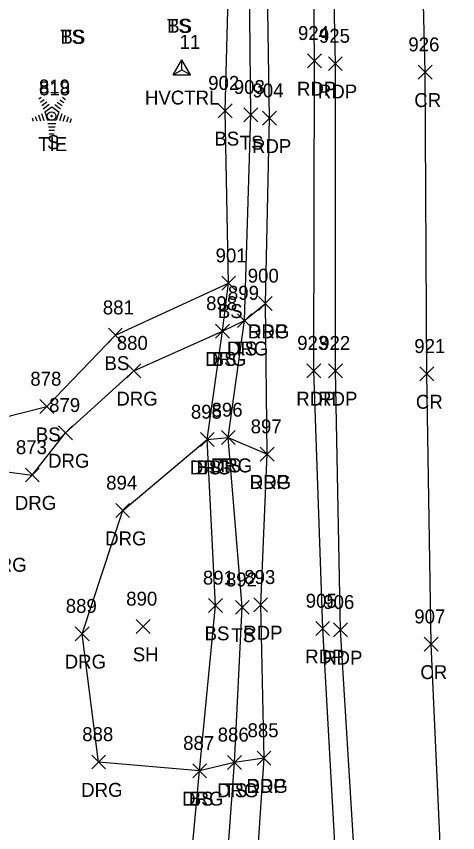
# Model space of a CAD drawing. Extents: x 1482574 to 1485769, y 580696 to 595649.
# Drawn here: x 1483637.4 to 1483700.8, y 584637.7 to 584755 of the extents above; entities that cross this region are included whole.
import ezdxf

# ---------------------------------------------------------------- set-up
doc = ezdxf.new("R2010")
doc.units = 0
for name, color, linetype in [('C_A', 7, 'Continuous'), ('C_I', 7, 'Continuous'), ('CBP', 7, 'Continuous'), ('CPSM', 7, 'Continuous'), ('L_A', 7, 'Continuous'), ('L_I', 7, 'Continuous'), ('L_TIC', 7, 'Continuous'), ('LELB', 7, 'Continuous'), ('LTC', 7, 'Continuous'), ('P_A', 7, 'Continuous'), ('P_I', 7, 'Continuous'), ('P_TIC', 7, 'Continuous'), ('PET', 7, 'Continuous'), ('PRC', 7, 'Continuous'), ('R_A', 7, 'Continuous'), ('R_I', 7, 'Continuous'), ('R_TIC', 7, 'Continuous'), ('RDG', 7, 'Continuous')]:
    doc.layers.add(name, color=color, linetype=linetype)

msp = doc.modelspace()

# ---------------------------------------------------------------- linework, layer by layer
at = {"layer": 'CBP'}
for radius in [0.625, 0.0833]:
    msp.add_circle((1483642.44, 584740.63), radius, dxfattribs=at)
at = {"layer": 'CPSM'}
for p, q in [((1483659.91, 584746.58), (1483661.16, 584748.75)), ((1483662.41, 584746.58), (1483661.16, 584748.75)), ((1483661.16, 584747.31), (1483661.16, 584748.75)), ((1483659.91, 584746.58), (1483661.16, 584747.31)), ((1483661.16, 584747.31), (1483661.16, 584747.31)), ((1483661.16, 584747.31), (1483662.41, 584746.58)), ((1483659.91, 584746.58), (1483662.41, 584746.58))]:
    msp.add_line(p, q, dxfattribs=at)
at = {"layer": 'L_TIC'}
for points in [[(1483666.38, 584740.41), (1483668.38, 584742.41)], [(1483668.38, 584740.41), (1483666.38, 584742.41)], [(1483670.07, 584739.83), (1483672.07, 584741.83)], [(1483672.07, 584739.83), (1483670.07, 584741.83)], [(1483666.88, 584715.64), (1483668.88, 584717.64)], [(1483668.88, 584715.64), (1483666.88, 584717.64)], [(1483666.88, 584715.64), (1483668.88, 584717.64)], [(1483668.88, 584715.64), (1483666.88, 584717.64)], [(1483669.14, 584710.27), (1483671.14, 584712.27)], [(1483671.14, 584710.27), (1483669.14, 584712.27)], [(1483666, 584708.77), (1483668, 584710.77)], [(1483668, 584708.77), (1483666, 584710.77)], [(1483650.6, 584708.17), (1483652.6, 584710.17)], [(1483652.6, 584708.17), (1483650.6, 584710.17)], [(1483640.74, 584697.93), (1483642.74, 584699.93)], [(1483642.74, 584697.93), (1483640.74, 584699.93)], [(1483666.83, 584693.48), (1483668.83, 584695.48)], [(1483668.83, 584693.48), (1483666.83, 584695.48)], [(1483663.81, 584693.19), (1483665.81, 584695.19)], [(1483665.81, 584693.19), (1483663.81, 584695.19)], [(1483664.98, 584669.36), (1483666.98, 584671.36)], [(1483666.98, 584669.36), (1483664.98, 584671.36)], [(1483668.84, 584669.1), (1483670.84, 584671.1)], [(1483670.84, 584669.1), (1483668.84, 584671.1)], [(1483654.61, 584666.34), (1483656.61, 584668.34)], [(1483656.61, 584666.34), (1483654.61, 584668.34)], [(1483667.72, 584646.82), (1483669.72, 584648.82)], [(1483669.72, 584646.82), (1483667.72, 584648.82)], [(1483662.71, 584645.62), (1483664.71, 584647.62)], [(1483664.71, 584645.62), (1483662.71, 584647.62)]]:
    msp.add_lwpolyline(points, dxfattribs=at)
at = {"layer": 'LELB'}
for points in [[(1483653.84, 584485.66), (1483655.16, 584497.25), (1483655.54, 584508.04), (1483660.89, 584522.88), (1483662.01, 584542.56), (1483663.9, 584573.36), (1483665.25, 584597.52), (1483666.54, 584618.22), (1483668.72, 584647.82), (1483669.84, 584670.1), (1483667.83, 584694.48), (1483670.14, 584711.27), (1483671.07, 584740.83), (1483670.56, 584792.73), (1483669.11, 584848.72), (1483666.77, 584902.21), (1483663.28, 584933.66), (1483662.05, 584942.07), (1483660.7, 584971.14), (1483662.19, 585003.59), (1483659.13, 585033.61), (1483657, 585045.7), (1483655.66, 585050.89), (1483655.43, 585083.72)], [(1483654.46, 584522.1), (1483653.65, 584530.37), (1483654.1, 584540.8), (1483656, 584573.95), (1483659.68, 584598.73), (1483657.74, 584615.24), (1483661.34, 584621.29), (1483663.71, 584646.62), (1483665.98, 584670.36), (1483664.81, 584694.19), (1483667, 584709.77), (1483667.88, 584716.64), (1483667.38, 584741.41), (1483668.7, 584792.15), (1483665.36, 584854.01), (1483663.91, 584902.17), (1483659.38, 584934.36), (1483656.14, 584945.72), (1483655.04, 584963.71), (1483656.17, 584970.54), (1483658.83, 585003.13), (1483656.92, 585033.59), (1483650.5, 585052.36), (1483650.21, 585078.55)], [(1483610.04, 584629.32), (1483609.43, 584646.28), (1483605.06, 584662.73), (1483601.74, 584679.59), (1483603.48, 584697.36), (1483628.88, 584695.71), (1483641.74, 584698.93), (1483651.6, 584709.17), (1483667.88, 584716.64)]]:
    msp.add_lwpolyline(points, dxfattribs=at)
at = {"layer": 'LTC'}
for p, q in [((1483640.61, 584743.11), (1483640.96, 584743.36)), ((1483640.82, 584742.64), (1483641.35, 584743.03)), ((1483641.03, 584742.18), (1483641.73, 584742.69)), ((1483641.24, 584741.71), (1483642.11, 584742.35)), ((1483642.89, 584742.3), (1483643.7, 584741.71)), ((1483643.26, 584742.65), (1483643.94, 584742.16)), ((1483643.63, 584743), (1483644.18, 584742.6)), ((1483644.01, 584743.35), (1483644.42, 584743.04)), ((1483641.46, 584741.25), (1483642.47, 584741.99)), ((1483641.46, 584741.25), (1483641.85, 584740.06)), ((1483642.47, 584741.99), (1483643.47, 584741.26)), ((1483643.47, 584741.26), (1483643.08, 584740.06)), ((1483639.64, 584740.39), (1483639.79, 584739.92)), ((1483640.1, 584740.6), (1483640.31, 584739.95)), ((1483640.55, 584740.82), (1483640.82, 584739.98)), ((1483641.01, 584741.04), (1483641.34, 584740.02)), ((1483643.08, 584740.06), (1483641.85, 584740.06)), ((1483643.91, 584740.99), (1483643.57, 584739.95)), ((1483644.35, 584740.74), (1483644.06, 584739.86)), ((1483644.8, 584740.49), (1483644.56, 584739.76)), ((1483645.24, 584740.24), (1483645.05, 584739.67)), ((1483643.04, 584739.56), (1483641.9, 584739.56)), ((1483642.96, 584739.06), (1483641.97, 584739.06)), ((1483642.87, 584738.56), (1483642.04, 584738.56)), ((1483642.79, 584738.06), (1483642.11, 584738.06))]:
    msp.add_line(p, q, dxfattribs=at)
at = {"layer": 'P_TIC'}
for points in [[(1483679.2, 584747.58), (1483681.2, 584749.58)], [(1483681.2, 584747.58), (1483679.2, 584749.58)], [(1483682.21, 584747.18), (1483684.21, 584749.18)], [(1483684.21, 584747.18), (1483682.21, 584749.18)], [(1483695.11, 584745.95), (1483697.11, 584747.95)], [(1483697.11, 584745.95), (1483695.11, 584747.95)], [(1483672.74, 584739.34), (1483674.74, 584741.34)], [(1483674.74, 584739.34), (1483672.74, 584741.34)], [(1483672.15, 584712.73), (1483674.15, 584714.73)], [(1483674.15, 584712.73), (1483672.15, 584714.73)], [(1483679.1, 584703.07), (1483681.1, 584705.07)], [(1483681.1, 584703.07), (1483679.1, 584705.07)], [(1483682.24, 584703.06), (1483684.24, 584705.06)], [(1483684.24, 584703.06), (1483682.24, 584705.06)], [(1483695.35, 584702.62), (1483697.35, 584704.62)], [(1483697.35, 584702.62), (1483695.35, 584704.62)], [(1483672.4, 584691.09), (1483674.4, 584693.09)], [(1483674.4, 584691.09), (1483672.4, 584693.09)], [(1483671.48, 584669.45), (1483673.48, 584671.45)], [(1483673.48, 584669.45), (1483671.48, 584671.45)], [(1483680.39, 584666.04), (1483682.39, 584668.04)], [(1483682.39, 584666.04), (1483680.39, 584668.04)], [(1483682.96, 584665.86), (1483684.96, 584667.86)], [(1483684.96, 584665.86), (1483682.96, 584667.86)], [(1483695.99, 584663.79), (1483697.99, 584665.79)], [(1483697.99, 584663.79), (1483695.99, 584665.79)], [(1483671.96, 584647.44), (1483673.96, 584649.44)], [(1483673.96, 584647.44), (1483671.96, 584649.44)]]:
    msp.add_lwpolyline(points, dxfattribs=at)
at = {"layer": 'PET'}
for points in [[(1483696.06, 584466.38), (1483697.12, 584483.5), (1483698.01, 584513.55), (1483697.99, 584538.32), (1483692.77, 584571.08), (1483691.88, 584578.27), (1483689.77, 584596.03), (1483686.09, 584631.8), (1483683.96, 584666.86), (1483683.24, 584704.06), (1483683.21, 584748.18), (1483682.28, 584793.9), (1483680.78, 584850.65), (1483678.8, 584902.92), (1483672.32, 584970.6), (1483669.68, 585004.19), (1483663.9, 585069.16), (1483661.29, 585125.32), (1483656.93, 585178.04), (1483653.35, 585225.15), (1483650.72, 585274.26)], [(1483647.15, 584246.07), (1483652.12, 584273.97), (1483655.81, 584298.41), (1483662.08, 584336.28), (1483668.63, 584381.65), (1483673.21, 584417.17), (1483676.95, 584449.39), (1483685.13, 584506.85), (1483688.62, 584539.16), (1483690.51, 584562.4), (1483689.87, 584577.41), (1483687.03, 584596.3), (1483683.38, 584631.91), (1483681.39, 584667.04), (1483680.1, 584704.07), (1483680.2, 584748.58), (1483679.79, 584793.53), (1483679.21, 584850.64), (1483677.2, 584902.59), (1483672.32, 584970.6)], [(1483625.23, 584246.59), (1483629.42, 584277.16), (1483633.34, 584303.63), (1483639.02, 584342.71), (1483643.26, 584374.14), (1483646.08, 584395.52), (1483650.14, 584421.13), (1483655.75, 584460.7), (1483661.86, 584509.33), (1483665.45, 584542.26), (1483667.26, 584573.1), (1483669.06, 584596.89), (1483670.57, 584612.73), (1483672.96, 584648.44), (1483672.48, 584670.45), (1483673.4, 584692.09), (1483673.15, 584713.73), (1483673.74, 584740.34), (1483672.92, 584793.11)]]:
    msp.add_lwpolyline(points, dxfattribs=at)
at = {"layer": 'PRC'}
msp.add_lwpolyline([(1483707.95, 584464.66), (1483709.57, 584481.33), (1483711.02, 584513.1), (1483710.87, 584539.52), (1483705.8, 584571.84), (1483702.27, 584596.86), (1483698.56, 584629.8), (1483696.99, 584664.79), (1483696.35, 584703.62), (1483696.11, 584746.95), (1483694.97, 584793.9), (1483693.55, 584850.21), (1483691.78, 584903.16), (1483687.15, 584966.03), (1483684.73, 584995.28), (1483678.25, 585070.79), (1483674.34, 585126.27), (1483669.53, 585178.97), (1483666.46, 585226.52), (1483663.26, 585274.78)], dxfattribs=at)
at = {"layer": 'R_TIC'}
for points in [[(1483672.15, 584712.73), (1483674.15, 584714.73)], [(1483674.15, 584712.73), (1483672.15, 584714.73)], [(1483669.14, 584710.27), (1483671.14, 584712.27)], [(1483671.14, 584710.27), (1483669.14, 584712.27)], [(1483666, 584708.77), (1483668, 584710.77)], [(1483668, 584708.77), (1483666, 584710.77)], [(1483653.25, 584703.07), (1483655.25, 584705.07)], [(1483655.25, 584703.07), (1483653.25, 584705.07)], [(1483643.45, 584694.15), (1483645.45, 584696.15)], [(1483645.45, 584694.15), (1483643.45, 584696.15)], [(1483666.83, 584693.48), (1483668.83, 584695.48)], [(1483668.83, 584693.48), (1483666.83, 584695.48)], [(1483663.81, 584693.19), (1483665.81, 584695.19)], [(1483665.81, 584693.19), (1483663.81, 584695.19)], [(1483672.4, 584691.09), (1483674.4, 584693.09)], [(1483674.4, 584691.09), (1483672.4, 584693.09)], [(1483638.67, 584688.1), (1483640.67, 584690.1)], [(1483640.67, 584688.1), (1483638.67, 584690.1)], [(1483651.65, 584683), (1483653.65, 584685)], [(1483653.65, 584683), (1483651.65, 584685)], [(1483645.84, 584665.3), (1483647.84, 584667.3)], [(1483647.84, 584665.3), (1483645.84, 584667.3)], [(1483648.2, 584646.88), (1483650.2, 584648.88)], [(1483650.2, 584646.88), (1483648.2, 584648.88)], [(1483667.72, 584646.82), (1483669.72, 584648.82)], [(1483669.72, 584646.82), (1483667.72, 584648.82)], [(1483671.96, 584647.44), (1483673.96, 584649.44)], [(1483673.96, 584647.44), (1483671.96, 584649.44)], [(1483662.71, 584645.62), (1483664.71, 584647.62)], [(1483664.71, 584645.62), (1483662.71, 584647.62)]]:
    msp.add_lwpolyline(points, dxfattribs=at)
at = {"layer": 'RDG'}
for points in [[(1483670.57, 584612.73), (1483666.54, 584618.22), (1483661.34, 584621.29), (1483651.01, 584624.93), (1483620.41, 584623.92), (1483617.87, 584643.56), (1483630.72, 584645.5), (1483631.54, 584665.65), (1483635.42, 584680.21), (1483630.05, 584681.03), (1483630.99, 584690.24), (1483639.67, 584689.1), (1483644.45, 584695.15), (1483654.25, 584704.07), (1483667, 584709.77), (1483670.14, 584711.27), (1483673.15, 584713.73)], [(1483672.96, 584648.44), (1483668.72, 584647.82), (1483663.71, 584646.62), (1483649.2, 584647.88), (1483646.84, 584666.3), (1483652.65, 584684), (1483664.81, 584694.19), (1483667.83, 584694.48), (1483673.4, 584692.09)]]:
    msp.add_lwpolyline(points, dxfattribs=at)

# ---------------------------------------------------------------- texts
at = {"layer": 'C_A'}
for s, p in [('HVCTRL', (1483655.85, 584742.31)), ('TIE', (1483640.52, 584735.63))]:
    msp.add_text(s, height=2, dxfattribs=at).set_placement(p)
at = {"layer": 'C_I'}
for s, p in [('11', (1483660.82, 584750.31)), ('818', (1483640.64, 584743.63))]:
    msp.add_text(s, height=2, dxfattribs=at).set_placement(p)
at = {"layer": 'L_A'}
for s, p in [('TS', (1483659.01, 584752.61)), ('BS', (1483659.04, 584752.61)), ('TS', (1483643.68, 584751.04)), ('BS', (1483643.71, 584751.04)), ('S', (1483641.8, 584735.9)), ('BS', (1483665.82, 584736.41)), ('TS', (1483669.47, 584735.83)), ('BS', (1483666.32, 584711.64)), ('BS', (1483666.32, 584711.64)), ('TS', (1483668.55, 584706.27)), ('BS', (1483650.04, 584704.17)), ('BS', (1483665.44, 584704.77)), ('BS', (1483640.18, 584693.93)), ('BS', (1483663.25, 584689.19)), ('TS', (1483666.24, 584689.48)), ('BS', (1483664.42, 584665.36)), ('TS', (1483668.25, 584665.1)), ('SH', (1483654.1, 584662.34)), ('TS', (1483667.13, 584642.82)), ('BS', (1483662.15, 584641.62))]:
    msp.add_text(s, height=2, dxfattribs=at).set_placement(p)
at = {"layer": 'L_I'}
for s, p in [('819', (1483640.61, 584743.9)), ('902', (1483664.94, 584744.41)), ('903', (1483668.62, 584743.83)), ('901', (1483666, 584719.64)), ('901', (1483666, 584719.64)), ('899', (1483667.77, 584714.27)), ('881', (1483649.8, 584712.17)), ('898', (1483664.64, 584712.77)), ('878', (1483639.38, 584701.93)), ('895', (1483662.45, 584697.19)), ('896', (1483665.42, 584697.48)), ('891', (1483664.18, 584673.36)), ('892', (1483667.48, 584673.1)), ('890', (1483653.16, 584670.34)), ('886', (1483666.3, 584650.82)), ('887', (1483661.34, 584649.62))]:
    msp.add_text(s, height=2, dxfattribs=at).set_placement(p)
at = {"layer": 'LTC'}
msp.add_text('.', height=1.04, rotation=270, dxfattribs=at).set_placement((1483642.35, 584741))
at = {"layer": 'P_A'}
for s, p in [('RDP', (1483677.69, 584743.58)), ('RDP', (1483680.7, 584743.18)), ('CR', (1483694.55, 584741.95)), ('RDP', (1483671.23, 584735.34)), ('RDP', (1483670.64, 584708.73)), ('RDP', (1483677.59, 584699.07)), ('RDP', (1483680.73, 584699.06)), ('CR', (1483694.78, 584698.62)), ('RDP', (1483670.89, 584687.09)), ('RDP', (1483669.97, 584665.45)), ('RDP', (1483678.88, 584662.04)), ('RDP', (1483681.45, 584661.86)), ('CR', (1483695.42, 584659.79)), ('RDP', (1483670.44, 584643.44))]:
    msp.add_text(s, height=2, dxfattribs=at).set_placement(p)
at = {"layer": 'P_I'}
for s, p in [('924', (1483677.84, 584751.58)), ('925', (1483680.85, 584751.18)), ('926', (1483693.7, 584749.95)), ('904', (1483671.3, 584743.34)), ('900', (1483670.62, 584716.73)), ('923', (1483677.73, 584707.07)), ('922', (1483680.88, 584707.06)), ('921', (1483694.55, 584706.62)), ('897', (1483671.04, 584695.09)), ('893', (1483670.12, 584673.45)), ('905', (1483678.95, 584670.04)), ('906', (1483681.47, 584669.86)), ('907', (1483694.55, 584667.79)), ('885', (1483670.59, 584651.44))]:
    msp.add_text(s, height=2, dxfattribs=at).set_placement(p)
at = {"layer": 'R_A'}
for p in [(1483670.64, 584708.73), (1483667.63, 584706.27), (1483664.49, 584704.77), (1483651.74, 584699.07), (1483641.93, 584690.15), (1483662.3, 584689.19), (1483665.32, 584689.48), (1483670.89, 584687.09), (1483637.16, 584684.1), (1483650.13, 584679), (1483632.91, 584675.21), (1483644.32, 584661.3), (1483670.44, 584643.44), (1483646.69, 584642.88), (1483666.21, 584642.82), (1483661.19, 584641.62)]:
    msp.add_text('DRG', height=2, dxfattribs=at).set_placement(p)
at = {"layer": 'R_I'}
for s, p in [('900', (1483670.62, 584716.73)), ('899', (1483667.77, 584714.27)), ('898', (1483664.64, 584712.77)), ('880', (1483651.8, 584707.07)), ('879', (1483642.08, 584698.15)), ('895', (1483662.45, 584697.19)), ('896', (1483665.42, 584697.48)), ('897', (1483671.04, 584695.09)), ('873', (1483637.31, 584692.1)), ('894', (1483650.28, 584687)), ('889', (1483644.47, 584669.3)), ('885', (1483670.59, 584651.44)), ('888', (1483646.84, 584650.88)), ('886', (1483666.3, 584650.82)), ('887', (1483661.34, 584649.62))]:
    msp.add_text(s, height=2, dxfattribs=at).set_placement(p)

doc.saveas('drawing.dxf')
